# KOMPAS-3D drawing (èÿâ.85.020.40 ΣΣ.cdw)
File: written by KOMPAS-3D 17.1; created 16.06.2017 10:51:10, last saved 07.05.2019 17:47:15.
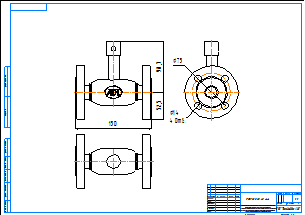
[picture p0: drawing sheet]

Sheet 1: A2, landscape

Title block, sheet 1: name: КШГ.85.020.40 фф; material: Внимание! Данный продукт является объектом авторского права ООО «Торговый Дом АДЛ». / Запрещается изменение, копирование, распространение / (в том числе путем копирования на другие сайты и ресурсы в Интернете) / или любое иное использование информации и объектов без предварительного / согласия правообладателя (ООО «Торговый Дом АДЛ»).; scale: 1:1; sheets: 1; organisation: ООО "Торговый дом АДЛ"; sheet format: A2; stored path: C:\Users\tra\Desktop\2д чертежи\Шаровые краны БИВАЛ\КШ_Бивал_серия_82_85\KOMPAS 2D\КШГ.85.020.40 фф.cdw

Views: Спереди 1, Проекционный вид 2, Проекционный вид 3
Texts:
  Klimkovich
  ADL
Dimensions and other numbers on the sheet: 150; 98,7; 52,5; 75; 14; 4 Отв.; 1:1; 1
